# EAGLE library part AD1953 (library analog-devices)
SigmaDSP (TM) 3-Channel, 26-Bit Signal Processing DAC Auto generated by make-symbol-device-package-bsdl.ulp Rev. 33 Source: http://www.analog.com/static/imported-files/data_sheets/AD1953.pdf
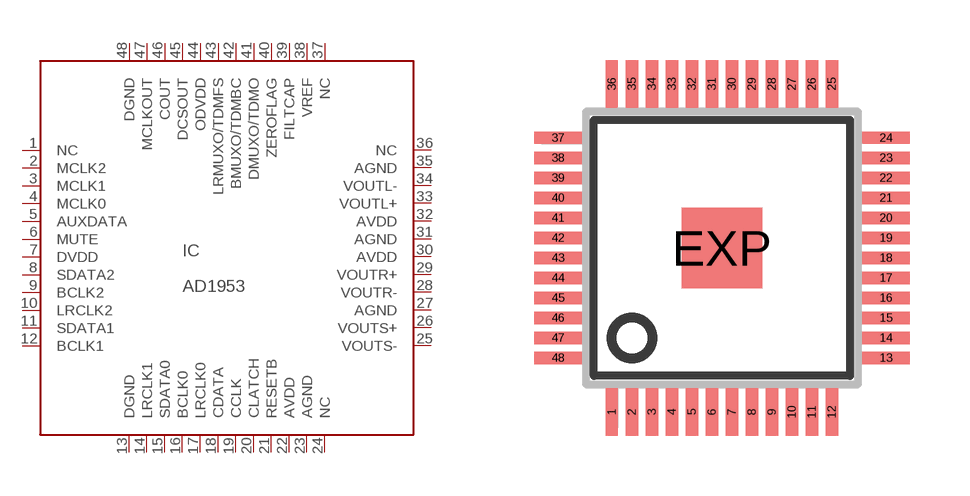
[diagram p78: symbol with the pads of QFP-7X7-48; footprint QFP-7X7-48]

Designator prefix IC

## AD1953 (MPN: AD1953YSTZRL7; OC_FARNELL: unknown; OC_NEWARK: 12M8457)  [QFP-7X7-48]
1  NC  nc
2  MCLK2  in
3  MCLK1  in
4  MCLK0  in
5  AUXDATA  in
6  MUTE  in
7  DVDD  pwr
8  SDATA2  in
9  BCLK2  in
10  LRCLK2  in
11  SDATA1  in
12  BCLK1  in
13  DGND  pwr
14  LRCLK1  in
15  SDATA0  in
16  BCLK0  in
17  LRCLK0  in
18  CDATA  in
19  CCLK  in
20  CLATCH  in
21  RESETB  in
22  AVDD  pwr
23  AGND  pwr
24  NC  nc
25  VOUTS-  out
26  VOUTS+  out
27  AGND  pwr
28  VOUTR-  out
29  VOUTR+  out
30  AVDD  pwr
31  AGND  pwr
32  AVDD  pwr
33  VOUTL+  out
34  VOUTL-  out
35  AGND  pwr
36  NC  nc
37  NC  nc
38  VREF  in
39  FILTCAP  in
40  ZEROFLAG  out
41  DMUXO/TDMO  out
42  BMUXO/TDMBC  out
43  LRMUXO/TDMFS  out
44  ODVDD  pwr
45  DCSOUT  out
46  COUT  out
47  MCLKOUT  out
48  DGND  pwr

## Footprint QFP-7X7-48 (pad centres in mm)
TQFP48 7x7 Thin Plastic Quad Flat Package, Exposed Pad, TQFP/EP Source: www.analog.com/UploadedFiles/Data_Sheets/33830397585263AD9859_0.pdf
smd 0.3 x 1.2: 1 -2.75,-4.1; 2 -2.25,-4.1; 3 -1.75,-4.1; 4 -1.25,-4.1; 5 -0.75,-4.1; 6 -0.25,-4.1; 7 0.25,-4.1; 8 0.75,-4.1; 9 1.25,-4.1; 10 1.75,-4.1; 11 2.25,-4.1; 12 2.75,-4.1; 25 2.75,4.1; 26 2.25,4.1; 27 1.75,4.1; 28 1.25,4.1; 29 0.75,4.1; 30 0.25,4.1; 31 -0.25,4.1; 32 -0.75,4.1; 33 -1.25,4.1; 34 -1.75,4.1; 35 -2.25,4.1; 36 -2.75,4.1
smd 1.2 x 0.3: 13 4.1,-2.75; 14 4.1,-2.25; 15 4.1,-1.75; 16 4.1,-1.25; 17 4.1,-0.75; 18 4.1,-0.25; 19 4.1,0.25; 20 4.1,0.75; 21 4.1,1.25; 22 4.1,1.75; 23 4.1,2.25; 24 4.1,2.75; 37 -4.1,2.75; 38 -4.1,2.25; 39 -4.1,1.75; 40 -4.1,1.25; 41 -4.1,0.75; 42 -4.1,0.25; 43 -4.1,-0.25; 44 -4.1,-0.75; 45 -4.1,-1.25; 46 -4.1,-1.75; 47 -4.1,-2.25; 48 -4.1,-2.75
smd 2 x 2: EXP 0,0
